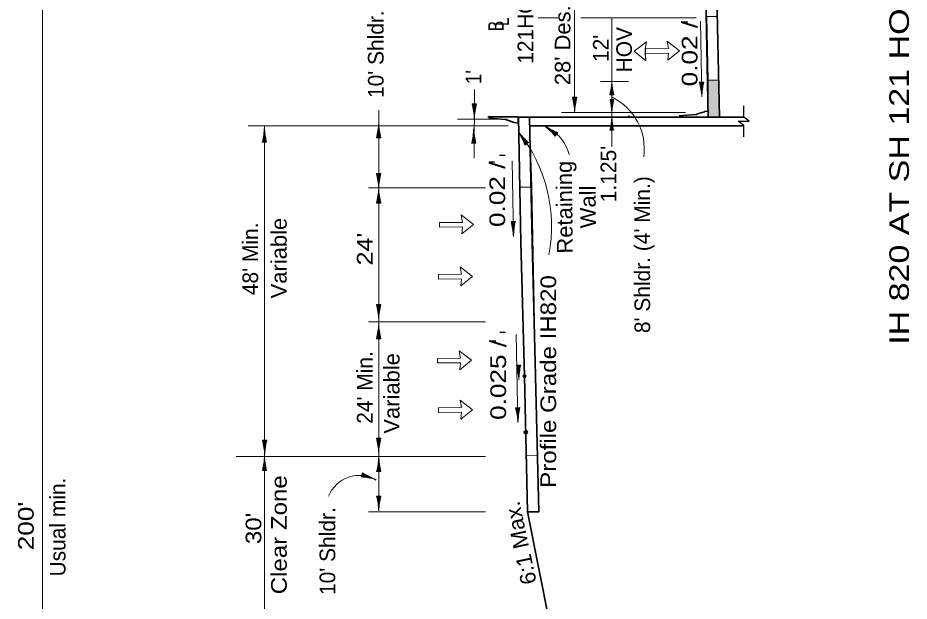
# Model space of a CAD drawing. Extents: x 2363427 to 2368559, y 6957299 to 6980140.
# Drawn here: x 2363666 to 2364464, y 6960819 to 6961341 of the extents above; entities that cross this region are included whole.
import ezdxf
from ezdxf.enums import TextEntityAlignment as Align

# ---------------------------------------------------------------- set-up
doc = ezdxf.new("R2010")
doc.units = 0
doc.header["$LTSCALE"] = 5.6
doc.header["$PDMODE"] = 32
doc.header["$PDSIZE"] = 2.8
for name, color, linetype, lineweight in [('3', 7, 'Continuous', 35), ('4', 7, 'Continuous', 13), ('40', 7, 'Continuous', 35), ('48', 7, 'Continuous', 25), ('8', 7, 'Continuous', 13)]:
    doc.layers.add(name, color=color, linetype=linetype, lineweight=lineweight)

msp = doc.modelspace()

# ---------------------------------------------------------------- hatches: boundary and pattern name
at = {"layer": '3'}
msp.add_hatch(color=256, dxfattribs=at).paths.add_polyline_path([(2364284.017, 6961252.102), (2364294.019, 6961252.201), (2364293.595, 6961285.384), (2364284.106, 6961285.384)])

# ---------------------------------------------------------------- linework, layer by layer
for p, q in [((2364281.524, 6961377.102), (2364284.017, 6961252.102)), ((2364291.525, 6961377.201), (2364294.019, 6961252.201)), ((2364274.467, 6961255.107), (2364280.58, 6961257.149)), ((2364280.745, 6961257.214), (2364280.755, 6961257.239)), ((2364284.017, 6961257.727), (2364280.755, 6961257.239)), ((2364284.017, 6961257.727), (2364280.951, 6961257.268)), ((2364284.017, 6961257.727), (2364284.017, 6961252.102)), ((2364086.717, 6961252.573), (2364113.787, 6961252.573)), ((2364102.447, 6961250.096), (2364087.744, 6961251.331)), ((2364104.236, 6961249.567), (2364110.349, 6961247.525)), ((2364113.787, 6961246.947), (2364113.787, 6961252.573)), ((2364315.743, 6961252.102), (2364114.182, 6961252.102)), ((2364124.184, 6961252.102), (2364126.411, 6961140.473)), ((2364212.451, 6961252.503), (2364212.451, 6961252.102)), ((2364256.947, 6961252.102), (2364284.017, 6961252.102)), ((2364272.678, 6961254.579), (2364257.975, 6961253.343)), ((2364110.514, 6961247.461), (2364110.524, 6961247.435)), ((2364113.787, 6961246.947), (2364110.524, 6961247.435)), ((2364113.787, 6961246.947), (2364110.721, 6961247.407)), ((2364315.743, 6961244.602), (2364124.333, 6961244.602)), ((2364126.409, 6961140.535), (2364129.542, 6961020.669)), ((2364119.545, 6961020.407), (2364122.377, 6960898.977)), ((2364129.543, 6961020.641), (2364132.377, 6960899.093)), ((2364132.379, 6960898.977), (2364122.377, 6960898.977)), ((2364122.377, 6960898.977), (2364184.144, 6960586.891))]:
    msp.add_line(p, q, dxfattribs=at)
at = {"layer": '3', "lineweight": 13}
msp.add_line((2364227.615, 6961308.747), (2364227.577, 6961312.843), dxfattribs=at)
at = {"layer": '3', "lineweight": 25}
for p, q in [((2364315.743, 6961252.291), (2364315.743, 6961262.291)), ((2364320.743, 6961248.541), (2364315.743, 6961252.291)), ((2364310.743, 6961248.541), (2364320.743, 6961248.541)), ((2364315.743, 6961244.791), (2364310.743, 6961248.541)), ((2364315.743, 6961234.791), (2364315.743, 6961244.791))]:
    msp.add_line(p, q, dxfattribs=at)
at = {"layer": '3', "lineweight": 13}
for points in [[(2364284.106, 6961285.384), (2364293.595, 6961285.384), (2364292.33, 6961342.279), (2364282.841, 6961342.279)], [(2364228.082, 6961302.627), (2364217.695, 6961311.163), (2364228.795, 6961319.765), (2364227.587, 6961313.037)], [(2364284.017, 6961252.102), (2364294.019, 6961252.201), (2364293.595, 6961285.384), (2364284.106, 6961285.384)], [(2364115.385, 6961189.727), (2364126.115, 6961189.727), (2364124.184, 6961252.102), (2364114.182, 6961252.102)], [(2364122.377, 6960898.977), (2364132.377, 6960899.093), (2364130.993, 6960949.415), (2364121.378, 6960949.267)]]:
    msp.add_lwpolyline(points, close=True, dxfattribs=at)
for points in [[(2364227.587, 6961313.037), (2364228.795, 6961319.765), (2364217.695, 6961311.163), (2364228.082, 6961302.627), (2364217.695, 6961311.163)], [(2364217.695, 6961311.163), (2364228.082, 6961302.627), (2364227.549, 6961308.943)]]:
    msp.add_lwpolyline(points, dxfattribs=at)
at = {"layer": '3'}
msp.add_lwpolyline([(2364114.182, 6961252.102), (2364116.413, 6961140.273), (2364119.545, 6961020.407)], dxfattribs=at)
at = {"layer": '3', "lineweight": 13}
for centre, radius, start, end in [((2364175.386, 6961223.989), 51.398, 352.05258, 63.94775), ((2364009.762, 6961155.082), 134.048, 348.81232, 38.65072)]:
    msp.add_arc(centre, radius, start, end, dxfattribs=at)
at = {"layer": '3'}
for centre, radius, start, end in [((2364281.129, 6961256.082), 1.2, 98.51269, 117.22516), ((2364101.948, 6961245.121), 5, 62.77128, 84.26462), ((2364213.598, 6961252.15), 1.2, 95.72178, 162.90786), ((2364272.179, 6961259.554), 5, 275.73538, 297.22872), ((2364110.899, 6961248.593), 1.2, 242.77484, 261.48731)]:
    msp.add_arc(centre, radius, start, end, dxfattribs=at)
msp.add_point((2364120.715, 6960970.256), dxfattribs=at)
at = {"layer": '4'}
for p, q in [((2363688.107, 6960320.227), (2363688.107, 6961377.102)), ((2364149.457, 6961341.117), (2364131.856, 6961341.117)), ((2364273.24, 6961341.117), (2364170.105, 6961341.117)), ((2364197.652, 6961225.611), (2364197.835, 6961341.117)), ((2364278.288, 6961270.307), (2364277.214, 6961338.024)), ((2364212.727, 6961284.179), (2364187.591, 6961284.179)), ((2364197.793, 6961272.121), (2364197.793, 6961283.428)), ((2364276.162, 6961283.587), (2364279.991, 6961283.647)), ((2364276.512, 6961283.592), (2364276.537, 6961282.007)), ((2364277.012, 6961283.6), (2364277.08, 6961279.324)), ((2364277.512, 6961283.608), (2364277.629, 6961276.259)), ((2364278.012, 6961283.616), (2364278.211, 6961271.053)), ((2364278.512, 6961283.624), (2364278.649, 6961275.015)), ((2364279.011, 6961283.631), (2364279.089, 6961278.771)), ((2364279.511, 6961283.639), (2364279.549, 6961281.259)), ((2364074.641, 6961215.489), (2364074.738, 6961277.146)), ((2364196.443, 6961272.121), (2364196.443, 6961274.264)), ((2364196.893, 6961272.121), (2364196.893, 6961276.496)), ((2364197.343, 6961272.121), (2364197.343, 6961279.869)), ((2364198.243, 6961272.121), (2364198.243, 6961278.735)), ((2364198.693, 6961272.121), (2364198.693, 6961275.969)), ((2364199.143, 6961272.121), (2364199.143, 6961273.547)), ((2364162.562, 6961270.097), (2364166.392, 6961270.097)), ((2364162.912, 6961270.097), (2364162.912, 6961268.511)), ((2364163.412, 6961270.097), (2364163.412, 6961265.821)), ((2364163.912, 6961270.097), (2364163.912, 6961262.747)), ((2364164.412, 6961270.097), (2364164.412, 6961257.533)), ((2364164.912, 6961270.097), (2364164.912, 6961261.487)), ((2364165.412, 6961270.097), (2364165.412, 6961265.235)), ((2364165.912, 6961270.097), (2364165.912, 6961267.715)), ((2364199.458, 6961272.121), (2364196.011, 6961272.121)), ((2364196.145, 6961267.977), (2364199.401, 6961267.977)), ((2364196.443, 6961267.977), (2364196.443, 6961266.63)), ((2364196.867, 6961267.977), (2364196.867, 6961264.343)), ((2364197.293, 6961267.977), (2364197.293, 6961261.73)), ((2364197.717, 6961267.977), (2364197.717, 6961257.297)), ((2364198.143, 6961267.977), (2364198.143, 6961260.659)), ((2364198.567, 6961267.977), (2364198.567, 6961263.845)), ((2364198.993, 6961267.977), (2364198.993, 6961265.953)), ((2363989.056, 6961089.409), (2363989.056, 6961258.499)), ((2364072.753, 6961264.234), (2364076.583, 6961264.234)), ((2364073.103, 6961264.234), (2364073.103, 6961262.649)), ((2364073.603, 6961264.234), (2364073.603, 6961259.957)), ((2364074.103, 6961264.234), (2364074.103, 6961256.884)), ((2364074.603, 6961264.234), (2364074.603, 6961251.67)), ((2364075.103, 6961264.234), (2364075.103, 6961255.625)), ((2364075.603, 6961264.234), (2364075.603, 6961259.372)), ((2364076.103, 6961264.234), (2364076.103, 6961261.853)), ((2364103.972, 6961250.587), (2364059.632, 6961250.587)), ((2364263.537, 6961256.571), (2364152.817, 6961256.571)), ((2364197.782, 6961240.759), (2364197.782, 6961251.438)), ((2364104.927, 6961244.439), (2363872.253, 6961244.439)), ((2363886.888, 6961229.859), (2363886.888, 6961242.423)), ((2363886.923, 6960948.564), (2363886.923, 6961244.439)), ((2363988.621, 6961233.729), (2363988.621, 6961242.339)), ((2363989.121, 6961233.729), (2363989.121, 6961246.293)), ((2364074.241, 6961228.942), (2364074.241, 6961241.506)), ((2364148.193, 6961236.987), (2364137.952, 6961244.267)), ((2364147.903, 6961236.579), (2364140.886, 6961241.567)), ((2364148.483, 6961237.395), (2364142.492, 6961241.653)), ((2364196.507, 6961240.759), (2364196.507, 6961242.783)), ((2364196.932, 6961240.759), (2364196.932, 6961244.891)), ((2364197.357, 6961240.759), (2364197.357, 6961248.077)), ((2364198.207, 6961240.759), (2364198.207, 6961247.006)), ((2364198.632, 6961240.759), (2364198.632, 6961244.394)), ((2364199.057, 6961240.759), (2364199.057, 6961242.106)), ((2363885.888, 6961229.859), (2363885.888, 6961234.721)), ((2363886.388, 6961229.859), (2363886.388, 6961238.468)), ((2363887.388, 6961229.859), (2363887.388, 6961237.209)), ((2363887.888, 6961229.859), (2363887.888, 6961234.135)), ((2363990.971, 6961233.729), (2363987.141, 6961233.729)), ((2363987.621, 6961233.729), (2363987.621, 6961236.111)), ((2363988.121, 6961233.729), (2363988.121, 6961238.591)), ((2363989.621, 6961233.729), (2363989.621, 6961241.079)), ((2363990.121, 6961233.729), (2363990.121, 6961238.006)), ((2363990.621, 6961233.729), (2363990.621, 6961235.315)), ((2364073.241, 6961228.942), (2364073.241, 6961233.804)), ((2364073.741, 6961228.942), (2364073.741, 6961237.552)), ((2364074.741, 6961228.942), (2364074.741, 6961236.292)), ((2364075.241, 6961228.942), (2364075.241, 6961233.219)), ((2364121.65, 6961228.418), (2364114.472, 6961238.73)), ((2364121.239, 6961228.133), (2364116.321, 6961235.199)), ((2364122.06, 6961228.703), (2364117.861, 6961234.735)), ((2364147.613, 6961236.171), (2364143.651, 6961238.989)), ((2364148.772, 6961237.802), (2364145.287, 6961240.279)), ((2364147.324, 6961235.764), (2364145.383, 6961237.144)), ((2364149.265, 6961238.495), (2364147.046, 6961235.373)), ((2364149.062, 6961238.209), (2364147.77, 6961239.127)), ((2364199.355, 6961240.759), (2364196.099, 6961240.759)), ((2363888.738, 6961229.859), (2363884.908, 6961229.859)), ((2363885.388, 6961229.859), (2363885.388, 6961232.24)), ((2363888.388, 6961229.859), (2363888.388, 6961231.443)), ((2364076.091, 6961228.942), (2364072.261, 6961228.942)), ((2364072.741, 6961228.942), (2364072.741, 6961231.324)), ((2364075.741, 6961228.942), (2364075.741, 6961230.527)), ((2364120.829, 6961227.847), (2364118.051, 6961231.837)), ((2364120.419, 6961227.561), (2364119.058, 6961229.515)), ((2364123.168, 6961229.475), (2364120.025, 6961227.287)), ((2364122.471, 6961228.989), (2364120.027, 6961232.499)), ((2364122.881, 6961229.275), (2364121.975, 6961230.575)), ((2364109.691, 6961145.599), (2364108.617, 6961213.315)), ((2363987.141, 6961201.875), (2363990.971, 6961201.875)), ((2363987.491, 6961201.875), (2363987.491, 6961200.291)), ((2363987.991, 6961201.875), (2363987.991, 6961197.599)), ((2363988.491, 6961201.875), (2363988.491, 6961194.525)), ((2363988.991, 6961201.875), (2363988.991, 6961189.311)), ((2363989.491, 6961201.875), (2363989.491, 6961193.266)), ((2363989.991, 6961201.875), (2363989.991, 6961197.013)), ((2363990.491, 6961201.875), (2363990.491, 6961199.494)), ((2364084.711, 6961188.977), (2363979.804, 6961188.977)), ((2363989.121, 6961175.253), (2363989.121, 6961187.817)), ((2363987.621, 6961175.253), (2363987.621, 6961177.634)), ((2363988.121, 6961175.253), (2363988.121, 6961180.115)), ((2363988.621, 6961175.253), (2363988.621, 6961183.862)), ((2363989.621, 6961175.253), (2363989.621, 6961182.603)), ((2363990.121, 6961175.253), (2363990.121, 6961179.529)), ((2363990.971, 6961175.253), (2363987.141, 6961175.253)), ((2363990.621, 6961175.253), (2363990.621, 6961176.837)), ((2364107.565, 6961158.878), (2364111.394, 6961158.939)), ((2364107.565, 6961158.878), (2364111.394, 6961158.939)), ((2364107.915, 6961158.883), (2364107.939, 6961157.299)), ((2364107.915, 6961158.883), (2364107.939, 6961157.299)), ((2364108.415, 6961158.891), (2364108.483, 6961154.615)), ((2364108.415, 6961158.891), (2364108.483, 6961154.615)), ((2364108.915, 6961158.899), (2364109.031, 6961151.551)), ((2364108.915, 6961158.899), (2364109.031, 6961151.551)), ((2364109.415, 6961158.907), (2364109.613, 6961146.345)), ((2364109.415, 6961158.907), (2364109.613, 6961146.345)), ((2364109.915, 6961158.915), (2364110.051, 6961150.307)), ((2364109.915, 6961158.915), (2364110.051, 6961150.307)), ((2364110.414, 6961158.923), (2364110.491, 6961154.062)), ((2364110.414, 6961158.923), (2364110.491, 6961154.062)), ((2364110.914, 6961158.931), (2364110.952, 6961156.55)), ((2364110.914, 6961158.931), (2364110.952, 6961156.55)), ((2363987.141, 6961084.668), (2363990.971, 6961084.668)), ((2363987.491, 6961084.668), (2363987.491, 6961083.083)), ((2363987.991, 6961084.668), (2363987.991, 6961080.391)), ((2363988.491, 6961084.668), (2363988.491, 6961077.318)), ((2363988.991, 6961084.668), (2363988.991, 6961072.104)), ((2363989.056, 6960970.205), (2363989.056, 6961089.409)), ((2363989.491, 6961084.668), (2363989.491, 6961076.059)), ((2363989.991, 6961084.668), (2363989.991, 6961079.806)), ((2363990.491, 6961084.668), (2363990.491, 6961082.287)), ((2364084.711, 6961068.977), (2363979.804, 6961068.977)), ((2363989.121, 6961053.983), (2363989.121, 6961066.547)), ((2363988.121, 6961053.983), (2363988.121, 6961058.845)), ((2363988.621, 6961053.983), (2363988.621, 6961062.593)), ((2363989.621, 6961053.983), (2363989.621, 6961061.333)), ((2363990.121, 6961053.983), (2363990.121, 6961058.26)), ((2364113.745, 6960979.023), (2364112.133, 6961057.643)), ((2363990.971, 6961053.983), (2363987.141, 6961053.983)), ((2363987.621, 6961053.983), (2363987.621, 6961056.365)), ((2363990.621, 6961053.983), (2363990.621, 6961055.569)), ((2364112.335, 6961030.401), (2364116.165, 6961030.479)), ((2364112.685, 6961030.408), (2364112.717, 6961028.823)), ((2364113.185, 6961030.419), (2364113.273, 6961026.143)), ((2364113.685, 6961030.429), (2364113.835, 6961023.081)), ((2364114.185, 6961030.439), (2364114.442, 6961017.877)), ((2364114.685, 6961030.449), (2364114.861, 6961021.841)), ((2364115.185, 6961030.459), (2364115.284, 6961025.599)), ((2364115.685, 6961030.469), (2364115.733, 6961028.089)), ((2364111.557, 6960992.292), (2364115.387, 6960992.371)), ((2364111.907, 6960992.299), (2364111.939, 6960990.715)), ((2364112.407, 6960992.309), (2364112.495, 6960988.034)), ((2364112.907, 6960992.319), (2364113.057, 6960984.971)), ((2364113.407, 6960992.33), (2364113.664, 6960979.769)), ((2364113.907, 6960992.34), (2364114.083, 6960983.733)), ((2364114.407, 6960992.351), (2364114.506, 6960987.489)), ((2364114.907, 6960992.361), (2364114.955, 6960989.979)), ((2363989.113, 6960909.499), (2363989.113, 6960970.227)), ((2363885.065, 6960963.264), (2363888.895, 6960963.264)), ((2363885.415, 6960963.264), (2363885.415, 6960961.679)), ((2363885.915, 6960963.264), (2363885.915, 6960958.987)), ((2363886.415, 6960963.264), (2363886.415, 6960955.914)), ((2363886.915, 6960963.264), (2363886.915, 6960950.7)), ((2363887.415, 6960963.264), (2363887.415, 6960954.655)), ((2363887.915, 6960963.264), (2363887.915, 6960958.402)), ((2363888.415, 6960963.264), (2363888.415, 6960960.883)), ((2363987.141, 6960965.012), (2363990.971, 6960965.012)), ((2363987.491, 6960965.012), (2363987.491, 6960963.427)), ((2363987.991, 6960965.012), (2363987.991, 6960960.735)), ((2363988.491, 6960965.012), (2363988.491, 6960957.662)), ((2363988.991, 6960965.012), (2363988.991, 6960952.448)), ((2363989.491, 6960965.012), (2363989.491, 6960956.403)), ((2363989.991, 6960965.012), (2363989.991, 6960960.15)), ((2363990.491, 6960965.012), (2363990.491, 6960962.631)), ((2364084.767, 6960948.564), (2363861.371, 6960948.564)), ((2363886.88, 6960796.251), (2363886.88, 6960948.564)), ((2363886.945, 6960936.071), (2363886.945, 6960948.635)), ((2363989.178, 6960935.253), (2363989.178, 6960947.817)), ((2363885.445, 6960936.071), (2363885.445, 6960938.453)), ((2363885.945, 6960936.071), (2363885.945, 6960940.933)), ((2363886.445, 6960936.071), (2363886.445, 6960944.681)), ((2363887.445, 6960936.071), (2363887.445, 6960943.421)), ((2363887.945, 6960936.071), (2363887.945, 6960940.347)), ((2363988.178, 6960935.253), (2363988.178, 6960940.115)), ((2363988.678, 6960935.253), (2363988.678, 6960943.862)), ((2363989.678, 6960935.253), (2363989.678, 6960942.603)), ((2363990.178, 6960935.253), (2363990.178, 6960939.529)), ((2363888.795, 6960936.071), (2363884.965, 6960936.071)), ((2363888.445, 6960936.071), (2363888.445, 6960937.656)), ((2363973.427, 6960930.321), (2363974.592, 6960933.969)), ((2363973.533, 6960930.654), (2363975.043, 6960930.171)), ((2363973.685, 6960931.131), (2363977.759, 6960929.829)), ((2363973.837, 6960931.607), (2363980.839, 6960929.37)), ((2363973.989, 6960932.083), (2363985.958, 6960928.259)), ((2363974.141, 6960932.559), (2363982.343, 6960929.939)), ((2363974.294, 6960933.035), (2363978.925, 6960931.556)), ((2363974.446, 6960933.512), (2363976.715, 6960932.787)), ((2363991.028, 6960935.253), (2363987.198, 6960935.253)), ((2363987.678, 6960935.253), (2363987.678, 6960937.634)), ((2363990.678, 6960935.253), (2363990.678, 6960936.837)), ((2363987.198, 6960913.23), (2363991.028, 6960913.23)), ((2363987.548, 6960913.23), (2363987.548, 6960911.645)), ((2363988.048, 6960913.23), (2363988.048, 6960908.953)), ((2363988.548, 6960913.23), (2363988.548, 6960905.88)), ((2363989.048, 6960913.23), (2363989.048, 6960900.666)), ((2363989.548, 6960913.23), (2363989.548, 6960904.621)), ((2363990.048, 6960913.23), (2363990.048, 6960908.368)), ((2363990.548, 6960913.23), (2363990.548, 6960910.849)), ((2364084.571, 6960898.977), (2363979.804, 6960898.977))]:
    msp.add_line(p, q, dxfattribs=at)
at = {"layer": '4', "lineweight": 25}
for p, q in [((2364265.807, 6961337.4), (2364260.217, 6961337.4)), ((2364097.232, 6961218.381), (2364102.346, 6961218.381)), ((2364092.85, 6961212.055), (2364088.224, 6961212.055)), ((2364097.441, 6961059.928), (2364102.554, 6961059.928)), ((2364094.033, 6961051.898), (2364087.945, 6961051.898))]:
    msp.add_line(p, q, dxfattribs=at)
at = {"layer": '4'}
for points in [[(2364164.477, 6961256.571), (2364164.477, 6961307.014), (2364164.477, 6961371.477)], [(2364119.545, 6961020.407), (2364119.476, 6961020.553), (2364119.545, 6961020.407)]]:
    msp.add_lwpolyline(points, dxfattribs=at)
for centre, radius, start, end in [((2364132.823, 6961287.326), 64.991, 346.47039, 357.15644), ((2364262.646, 6961287.326), 64.991, 182.84356, 193.52961), ((2364206.23, 6961265.582), 72.212, 3.7522, 14.43825), ((2364350.459, 6961267.869), 72.212, 167.37903, 178.06508), ((2364092.353, 6961253.204), 72.212, 2.84356, 13.52961), ((2364236.6, 6961253.204), 72.212, 166.47039, 177.15644), ((2364136.468, 6961253.618), 61.381, 2.84356, 13.52961), ((2364259.078, 6961253.618), 61.381, 166.47039, 177.15644), ((2364002.545, 6961247.341), 72.212, 2.84356, 13.52961), ((2364146.792, 6961247.341), 72.212, 166.47039, 177.15644), ((2364136.421, 6961255.119), 61.381, 346.47039, 357.15644), ((2364259.031, 6961255.119), 61.381, 182.84356, 193.52961), ((2363814.699, 6961246.753), 72.212, 346.47039, 357.15644), ((2363958.947, 6961246.753), 72.212, 182.84356, 193.52961), ((2363916.932, 6961250.624), 72.212, 346.47039, 357.15644), ((2364061.18, 6961250.624), 72.212, 182.84356, 193.52961), ((2364002.052, 6961245.837), 72.212, 346.47039, 357.15644), ((2364146.299, 6961245.837), 72.212, 182.84356, 193.52961), ((2364176.172, 6961305.507), 72.212, 237.43652, 248.12257), ((2364092.598, 6961187.937), 72.212, 41.06336, 51.74941), ((2364125.544, 6961210.69), 34.94, 13.44028, 63.14536), ((2364171.14, 6961283.45), 72.212, 217.68394, 228.36999), ((2364052.75, 6961201.043), 72.212, 21.31077, 31.99682), ((2363916.932, 6961184.982), 72.212, 2.84356, 13.52961), ((2364061.18, 6961184.982), 72.212, 166.47039, 177.15644), ((2363916.932, 6961192.147), 72.212, 346.47039, 357.15644), ((2364061.18, 6961192.147), 72.212, 182.84356, 193.52961), ((2364037.633, 6961140.873), 72.212, 3.7522, 14.43825), ((2364037.633, 6961140.873), 72.212, 3.7522, 14.43825), ((2364181.862, 6961143.161), 72.212, 167.37903, 178.06508), ((2364181.862, 6961143.161), 72.212, 167.37903, 178.06508), ((2363916.932, 6961067.775), 72.212, 2.84356, 13.52961), ((2364061.18, 6961067.775), 72.212, 166.47039, 177.15644), ((2363916.932, 6961070.878), 72.212, 346.47039, 357.15644), ((2364061.18, 6961070.878), 72.212, 182.84356, 193.52961), ((2364042.488, 6961012.073), 72.212, 4.01743, 14.70348), ((2364186.704, 6961015.028), 72.212, 167.64427, 178.33032), ((2364041.709, 6960973.964), 72.212, 4.01743, 14.70348), ((2364185.926, 6960976.919), 72.212, 167.64427, 178.33032), ((2363814.857, 6960946.371), 72.212, 2.84356, 13.52961), ((2363959.104, 6960946.371), 72.212, 166.47039, 177.15644), ((2363916.932, 6960948.119), 72.212, 2.84356, 13.52961), ((2364061.18, 6960948.119), 72.212, 166.47039, 177.15644), ((2363814.756, 6960952.965), 72.212, 346.47039, 357.15644), ((2363959.004, 6960952.965), 72.212, 182.84356, 193.52961), ((2363916.989, 6960952.147), 72.212, 346.47039, 357.15644), ((2364061.237, 6960952.147), 72.212, 182.84356, 193.52961), ((2363971.67, 6960902.032), 29.635, 59.62074, 157.81619), ((2363968.154, 6960858.301), 72.212, 75.12659, 85.81264), ((2364012.05, 6960995.707), 72.212, 238.75343, 249.43948), ((2363916.989, 6960896.337), 72.212, 2.84356, 13.52961), ((2364061.237, 6960896.337), 72.212, 166.47039, 177.15644)]:
    msp.add_arc(centre, radius, start, end, dxfattribs=at)
msp.add_point((2364119.545, 6961020.407), dxfattribs=at)
at = {"layer": '40', "lineweight": 13}
for p, q in [((2364248.34, 6961313.553), (2364227.835, 6961313.357)), ((2364248.377, 6961309.457), (2364227.873, 6961309.263)), ((2364063.993, 6961154.041), (2364043.487, 6961153.847)), ((2364063.121, 6961107.53), (2364042.616, 6961107.335)), ((2364062.343, 6961032.496), (2364041.837, 6961032.301)), ((2364063.121, 6960988.236), (2364042.616, 6960988.041))]:
    msp.add_line(p, q, dxfattribs=at)
for points in [[(2364248.377, 6961309.457), (2364247.845, 6961303.143), (2364258.233, 6961311.677), (2364247.133, 6961320.28), (2364248.34, 6961313.553)], [(2364063.993, 6961154.041), (2364063.46, 6961147.727), (2364073.847, 6961156.261), (2364062.747, 6961164.864), (2364063.955, 6961158.137)], [(2364063.955, 6961158.137), (2364043.45, 6961157.941), (2364043.487, 6961153.847)], [(2364063.121, 6961107.53), (2364062.589, 6961101.215), (2364072.976, 6961109.75), (2364061.876, 6961118.353), (2364063.083, 6961111.625)], [(2364063.083, 6961111.625), (2364042.579, 6961111.43), (2364042.616, 6961107.335)], [(2364062.343, 6961032.496), (2364061.81, 6961026.181), (2364072.197, 6961034.716), (2364061.097, 6961043.319), (2364062.305, 6961036.591)], [(2364062.305, 6961036.591), (2364041.8, 6961036.396), (2364041.837, 6961032.301)], [(2364063.121, 6960988.236), (2364062.589, 6960981.921), (2364072.976, 6960990.456), (2364061.876, 6960999.059), (2364063.083, 6960992.331)], [(2364063.083, 6960992.331), (2364042.579, 6960992.136), (2364042.616, 6960988.041)]]:
    msp.add_lwpolyline(points, dxfattribs=at)
at = {"layer": '48', "lineweight": 13}
msp.add_lwpolyline([(2364121.378, 6960949.267), (2364130.993, 6960949.415), (2364126.115, 6961189.727), (2364115.385, 6961189.727)], close=True, dxfattribs=at)
at = {"layer": '8'}
for points in [[(2364258.233, 6961311.677), (2364247.845, 6961303.143), (2364248.377, 6961309.457), (2364227.873, 6961309.263), (2364227.835, 6961313.357), (2364248.34, 6961313.553), (2364247.133, 6961320.28)], [(2364073.847, 6961156.261), (2364063.46, 6961147.727), (2364063.993, 6961154.041), (2364043.487, 6961153.847), (2364043.45, 6961157.941), (2364063.955, 6961158.137), (2364062.747, 6961164.864)], [(2364072.976, 6961109.75), (2364062.589, 6961101.215), (2364063.121, 6961107.53), (2364042.616, 6961107.335), (2364042.579, 6961111.43), (2364063.083, 6961111.625), (2364061.876, 6961118.353)], [(2364072.197, 6961034.716), (2364061.81, 6961026.181), (2364062.343, 6961032.496), (2364041.837, 6961032.301), (2364041.8, 6961036.396), (2364062.305, 6961036.591), (2364061.097, 6961043.319)], [(2364072.976, 6960990.456), (2364062.589, 6960981.921), (2364063.121, 6960988.236), (2364042.616, 6960988.041), (2364042.579, 6960992.136), (2364063.083, 6960992.331), (2364061.876, 6960999.059)]]:
    msp.add_lwpolyline(points, close=True, dxfattribs=at)

# ---------------------------------------------------------------- texts
at = {"layer": '4'}
for s, height, rotation, width, p in [('IH 820 AT SH 121 HOV DIVERGE/MERGE', 17.5, 90, 1.3, (2364463.625, 6961341.891)), ("28' Des.", 14, 90, 1.05, (2364160.689, 6961316.604)), ('B', 14, 90, 0.75, (2364101.074, 6961333.851)), ('L', 14, 90, 0.75, (2364105.779, 6961337.657)), ('0.02 /', 14, 90, 1.25, (2364274.372, 6961309.083)), ("1' ", 14, 90, 0.9, (2364080.85, 6961290.407)), ('0.02 /', 14, 90, 1.25, (2364102.183, 6961183.244)), ('Retaining', 14, 90.665, 1.05, (2364162.344, 6961171.754)), ('Wall', 14, 90.665, 1.05, (2364183.341, 6961171.996)), ('Variable', 14, 90, 1.05, (2363906.73, 6961126.147)), ("24'", 14, 90, 1.2, (2363983.581, 6961134.224)), ('Profile Grade IH820', 14, 90, 1.15, (2364147.862, 6961015.735)), ('0.025 /', 14, 90, 1.25, (2364103.027, 6961017.144)), ('Variable', 14, 90, 1.05, (2364007.691, 6961005.096)), ('Clear Zone', 14, 90, 1.15, (2363906.787, 6960878.586)), ("200'", 14, 90, 1.25, (2363680.297, 6960886.456)), ('6:1 Max.', 14, 101.975, 1.05, (2364122.766, 6960872.599)), ("30'", 14, 90, 1.15, (2363884.021, 6960884.253))]:
    msp.add_text(s, height=height, rotation=rotation, dxfattribs=dict(at, width=width)).set_placement(p, align=Align.CENTER)
for s, p in [('121HOV', (2364127.371, 6961335.935)), ("10' Shldr.", (2363993.483, 6961308.639)), ('HOV', (2364215.745, 6961312.632)), ("12'", (2364194.867, 6961313.797)), ("1.125' ", (2364201.669, 6961203.992)), ("8' Shldr. (4' Min.)", (2364232.017, 6961129.193)), ("48' Min.", (2363881.113, 6961125.484)), ("24' Min.", (2363983.581, 6961010.367)), ('Usual min.', (2363708.755, 6960885.524)), ("10' Shldr.", (2363950.193, 6960863.964))]:
    msp.add_text(s, height=14, rotation=90, dxfattribs=at).set_placement(p, align=Align.CENTER)

doc.saveas('drawing.dxf')
